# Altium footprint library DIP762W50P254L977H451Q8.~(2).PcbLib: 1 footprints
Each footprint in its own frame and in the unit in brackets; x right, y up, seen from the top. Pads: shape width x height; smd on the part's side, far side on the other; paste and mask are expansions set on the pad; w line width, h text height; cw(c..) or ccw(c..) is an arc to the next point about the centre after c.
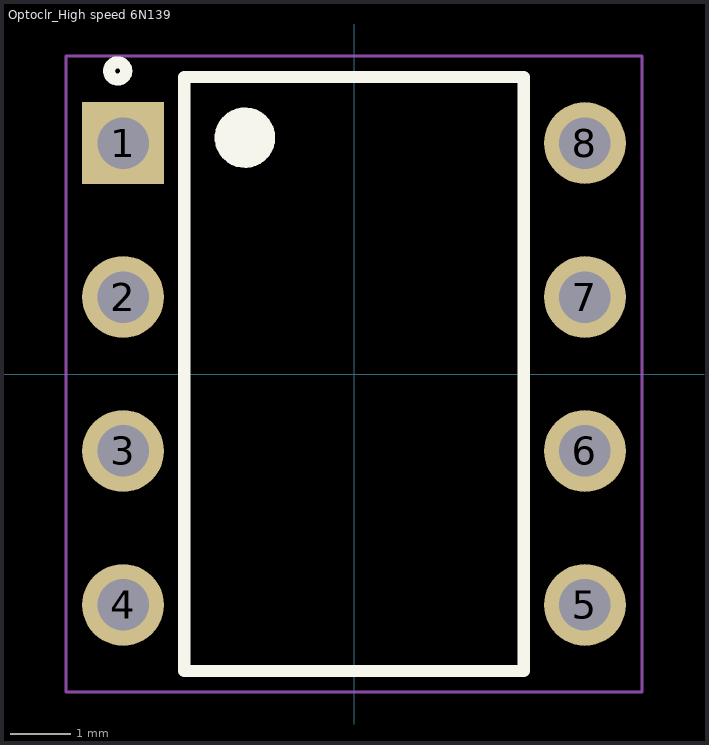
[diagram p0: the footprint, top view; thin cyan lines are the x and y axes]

## Optoclr_High speed 6N139 [mm] "Optoclr_High speed 6N139 DIP-8"
pads (8):
  rect 1.35x1.35 / inner round 1.35 / far side rect 1.35x1.35 hole 0.85: 1(-3.81,3.81)
  round 1.35 hole 0.85: 2(-3.81,1.27) 3(-3.81,-1.27) 4(-3.81,-3.81) 5(3.81,-3.81) 6(3.81,-1.27) 7(3.81,1.27) 8(3.81,3.81)
Top Overlay:
  circle w0.2: c-1.9,3.9 r0.141
  circle w0.2: c-1.7,3.9 r0.2
  circle w0.2: c-1.8,3.9 r0.224
  circle w0.2: c-3.9,5 r0.141
  circle w0.2: c-1.8,3.9 r0.4
  lines w0.2: -2.8,-4.9 -2.8,4.9 2.8,4.9 2.8,-4.9 -2.8,-4.9
Courtyard Top:
  lines w0.05: -4.75,-5.25 -4.75,5.25 4.75,5.25 4.75,-5.25 -4.75,-5.25
3D body "step_temp.STEP": height 5.08, standoff -3.9, extent -3.96,-4.828 3.96,4.828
